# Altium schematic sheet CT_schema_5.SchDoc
size 366 x 245 mm
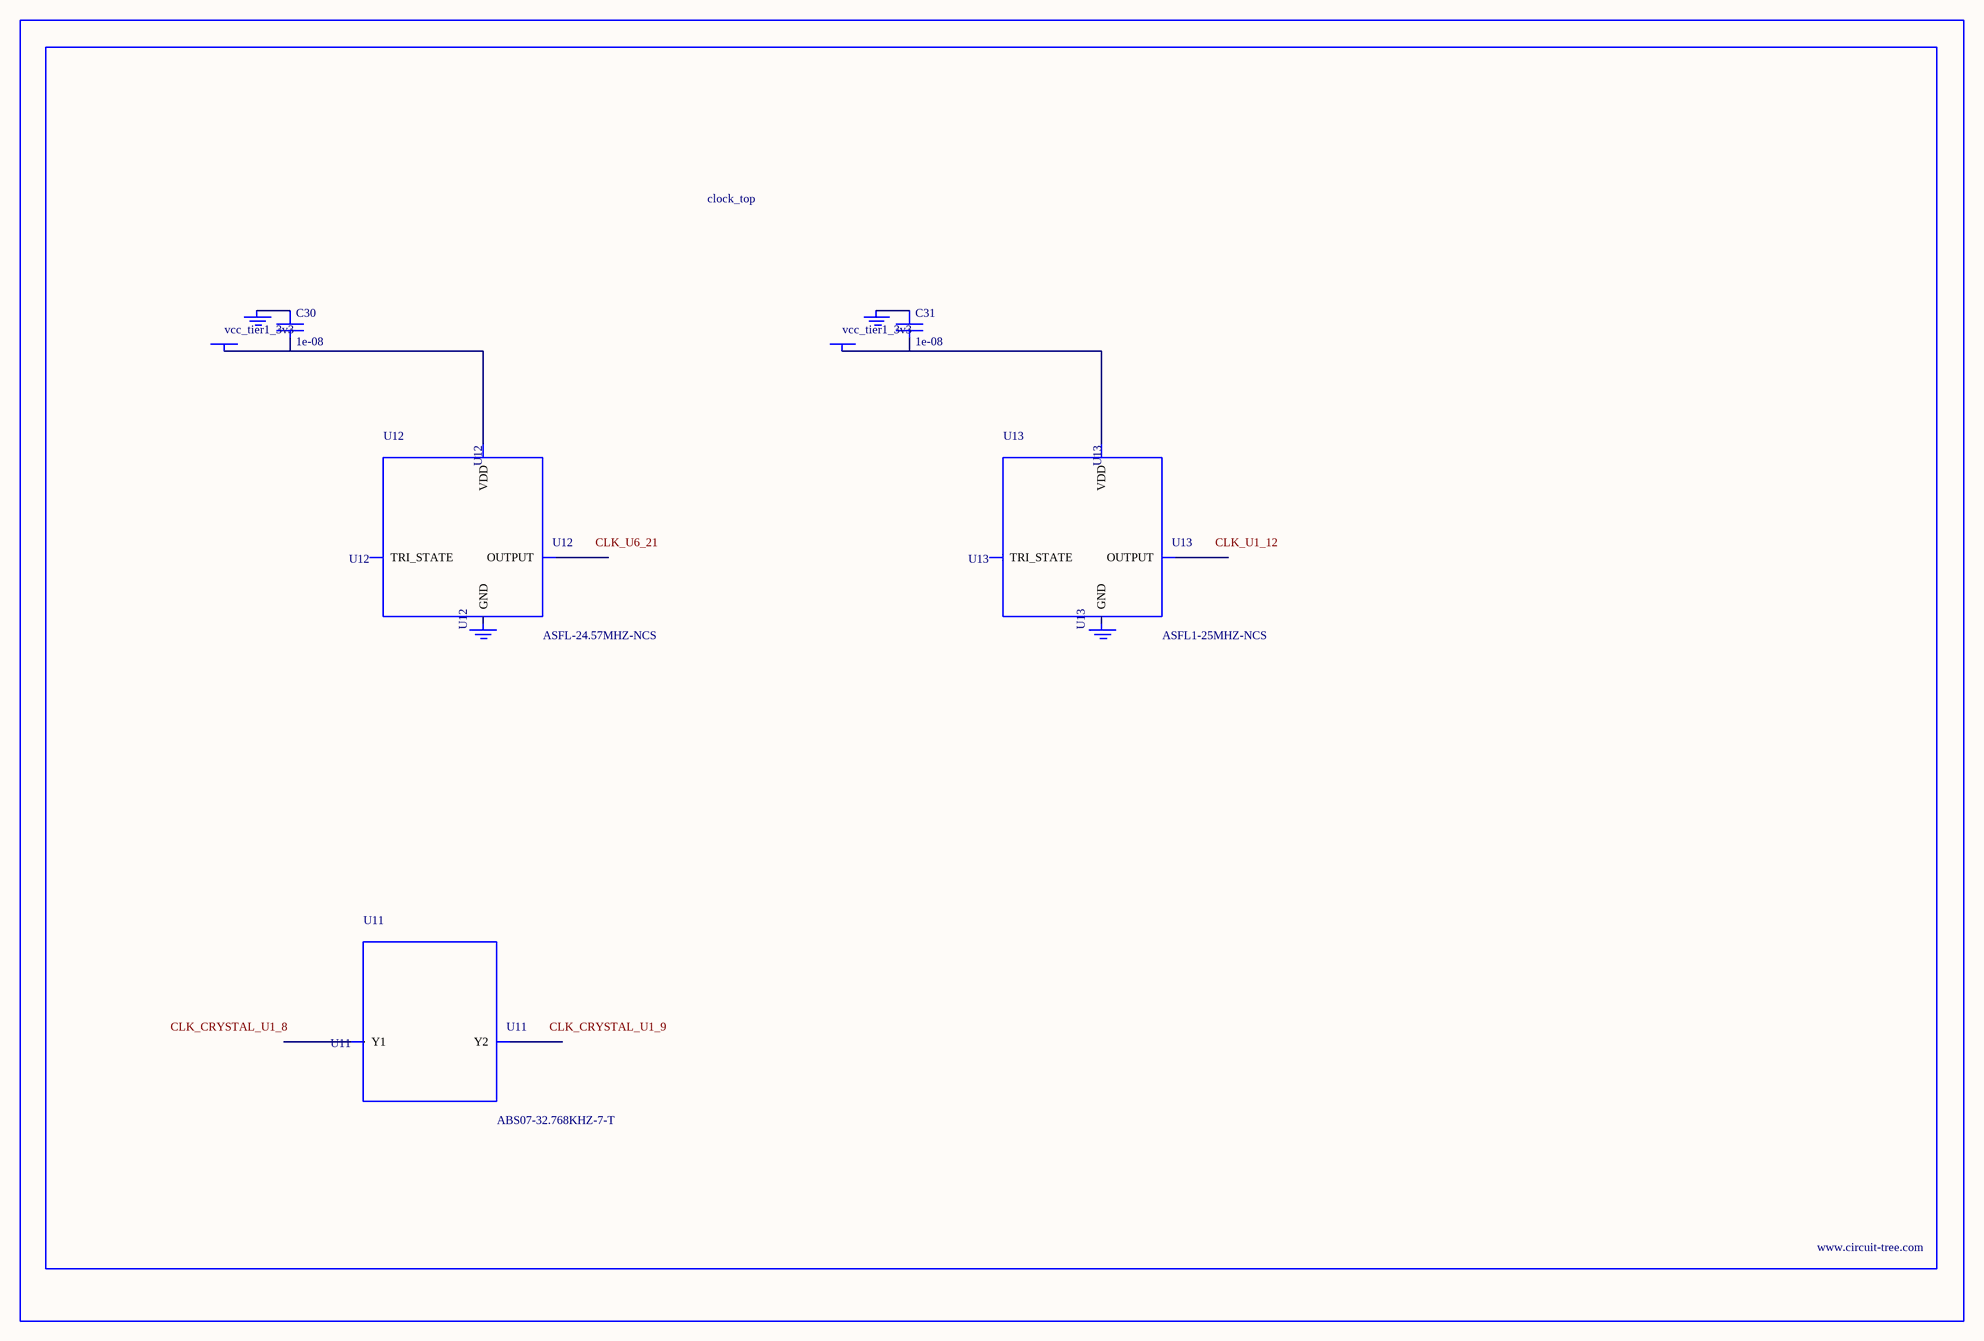
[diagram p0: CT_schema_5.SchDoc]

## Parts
BORDER4  (no value)
C30  1e-08  [C0402]
C31  1e-08  [C0402]
GND_INSTANCE_4_0  (no value)
GND_INSTANCE_4_1  (no value)
GND_INSTANCE_4_2  (no value)
GND_INSTANCE_4_3  (no value)
POWER_INSTANCE_4_0  vcc_tier1_3v3
POWER_INSTANCE_4_1  vcc_tier1_3v3
U11  ABS07-32.768KHZ-7-T  [ABS07-32.768KHZ-7-T]
U12  ASFL-24.57MHZ-NCS  [ASFL1]
U13  ASFL1-25MHZ-NCS  [ASFL1]

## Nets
NetC30_1: C30.1 GND_INSTANCE_4_0.0(GND)
NetC30_2: C30.2 POWER_INSTANCE_4_0.0(PWR) U12.4(VDD)
NetC31_1: C31.1 GND_INSTANCE_4_2.0(GND)
NetC31_2: C31.2 POWER_INSTANCE_4_1.0(PWR) U13.4(VDD)

Not connected (* = marked no-connect by the designer): GND_INSTANCE_4_1 0(GND); GND_INSTANCE_4_3 0(GND); U11 1(Y1) 2(Y2); U12 1(TRI_STATE) 2(GND) 3(OUTPUT); U13 1(TRI_STATE) 2(GND) 3(OUTPUT)

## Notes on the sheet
- Labels drawn without touching a wire or pin: CLK_CRYSTAL_U1_8, CLK_CRYSTAL_U1_9, CLK_U1_12, CLK_U6_21

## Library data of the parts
BORDER4 = BORDER_PAGE4
C30 C31 = C0402C103K3RAC
GND_INSTANCE_4_0-GND_INSTANCE_4_3 = GND
POWER_INSTANCE_4_0 POWER_INSTANCE_4_1 = PWR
